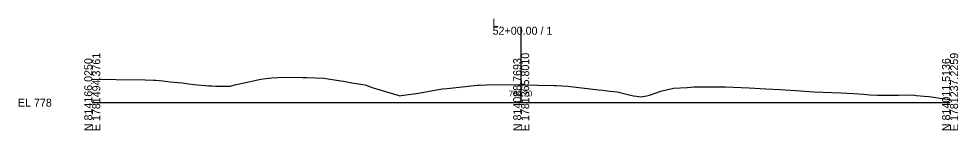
# Model space of a CAD drawing. Extents: x -26 to 7903, y -10 to 9573.
# Drawn here: x 1974.3 to 2302.8, y 2990.3 to 3029.4 of the extents above; entities that cross this region are included whole.
import ezdxf

# ---------------------------------------------------------------- set-up
doc = ezdxf.new("R2010")
doc.units = 0
for name, color, linetype in [('Exist Cross Section Cell', 7, 'Continuous'), ('Exist XS Center Line Elevation Label', 7, 'Continuous'), ('Exist XS Ground Line', 7, 'Continuous')]:
    doc.layers.add(name, color=color, linetype=linetype)

msp = doc.modelspace()

# ---------------------------------------------------------------- linework, layer by layer
at = {"layer": 'Exist Cross Section Cell'}
for p, q in [((2150, 3000), (2150, 3026.63)), ((2000, 3000), (2150, 3000)), ((2150, 3000), (2300, 3000))]:
    msp.add_line(p, q, dxfattribs=at)
at = {"layer": 'Exist XS Ground Line'}
for p, q in [((2000, 3008.11), (2006.24, 3008.2)), ((2006.24, 3008.2), (2008.4, 3008.17)), ((2008.4, 3008.17), (2018.52, 3008.04)), ((2018.52, 3008.04), (2021.46, 3007.89)), ((2021.46, 3007.89), (2022.12, 3007.86)), ((2022.12, 3007.86), (2024.74, 3007.6)), ((2024.74, 3007.6), (2027.24, 3007.27)), ((2027.24, 3007.27), (2031.44, 3006.93)), ((2031.44, 3006.93), (2033.77, 3006.64)), ((2033.77, 3006.64), (2035.53, 3006.38)), ((2035.53, 3006.38), (2040.77, 3005.93)), ((2048.29, 3005.8), (2049.88, 3006.21)), ((2049.88, 3006.21), (2052.52, 3006.83)), ((2052.52, 3006.83), (2059, 3008.25)), ((2059, 3008.25), (2060.66, 3008.51)), ((2060.66, 3008.51), (2062.84, 3008.67)), ((2062.84, 3008.67), (2064.95, 3008.87)), ((2064.95, 3008.87), (2068.12, 3008.88)), ((2068.12, 3008.88), (2073.37, 3008.86)), ((2073.37, 3008.86), (2075.04, 3008.83)), ((2075.04, 3008.83), (2081, 3008.58)), ((2081, 3008.58), (2086.99, 3007.61)), ((2086.99, 3007.61), (2087.84, 3007.48)), ((2087.84, 3007.48), (2090.8, 3006.98)), ((2090.8, 3006.98), (2095.48, 3006.27)), ((2095.48, 3006.27), (2098.19, 3005.24)), ((2134.58, 3006.07), (2135.28, 3006.15)), ((2135.28, 3006.15), (2137.85, 3006.3)), ((2137.85, 3006.3), (2138.44, 3006.33)), ((2138.44, 3006.33), (2150.01, 3006.2)), ((2150.01, 3006.2), (2161.41, 3006)), ((2040.77, 3005.93), (2041.69, 3005.84)), ((2041.69, 3005.84), (2043.16, 3005.76)), ((2043.16, 3005.76), (2047.49, 3005.73)), ((2047.49, 3005.73), (2048.29, 3005.8)), ((2098.19, 3005.24), (2100.21, 3004.58)), ((2100.21, 3004.58), (2104.89, 3003.19)), ((2104.89, 3003.19), (2106.89, 3002.66)), ((2108.04, 3002.46), (2114.15, 3003.35)), ((2114.15, 3003.35), (2120.42, 3004.5)), ((2120.42, 3004.5), (2122.43, 3004.89)), ((2122.43, 3004.89), (2124.12, 3005.01)), ((2124.12, 3005.01), (2133.6, 3005.98)), ((2133.6, 3005.98), (2134.58, 3006.07)), ((2161.41, 3006), (2162.25, 3005.98)), ((2162.25, 3005.98), (2166.26, 3005.75)), ((2166.26, 3005.75), (2177.01, 3004.5)), ((2177.01, 3004.5), (2178.55, 3004.33)), ((2178.55, 3004.33), (2181.01, 3004.08)), ((2181.01, 3004.08), (2183.54, 3003.77)), ((2183.54, 3003.77), (2187.79, 3002.79)), ((2194.83, 3002.64), (2198.82, 3003.97)), ((2198.82, 3003.97), (2203.29, 3005.12)), ((2203.29, 3005.12), (2208.03, 3005.33)), ((2208.03, 3005.33), (2210.41, 3005.49)), ((2210.41, 3005.49), (2219.06, 3005.53)), ((2219.06, 3005.53), (2219.6, 3005.55)), ((2219.6, 3005.55), (2221.51, 3005.57)), ((2221.51, 3005.57), (2229.73, 3005.25)), ((2229.73, 3005.25), (2235.55, 3004.86)), ((2235.55, 3004.86), (2240.55, 3004.66)), ((2240.55, 3004.66), (2247.74, 3004.11)), ((2247.74, 3004.11), (2252.4, 3003.84)), ((2252.4, 3003.84), (2261.77, 3003.43)), ((2261.77, 3003.43), (2264.02, 3003.34)), ((2264.02, 3003.34), (2266.17, 3003.15)), ((2266.17, 3003.15), (2269.87, 3002.93)), ((2269.87, 3002.93), (2271.94, 3002.71)), ((2106.89, 3002.66), (2107.59, 3002.38)), ((2107.59, 3002.38), (2108.04, 3002.46)), ((2187.79, 3002.79), (2189.34, 3002.44)), ((2189.34, 3002.44), (2190.31, 3002.29)), ((2190.31, 3002.29), (2192.02, 3002.06)), ((2192.02, 3002.06), (2193.85, 3002.41)), ((2193.85, 3002.41), (2194.83, 3002.64)), ((2271.94, 3002.71), (2274.57, 3002.62)), ((2274.57, 3002.62), (2277.6, 3002.62)), ((2277.6, 3002.62), (2280.51, 3002.62)), ((2280.51, 3002.62), (2281.91, 3002.65)), ((2281.91, 3002.65), (2287.1, 3002.72)), ((2287.1, 3002.72), (2288.22, 3002.51)), ((2288.22, 3002.51), (2290.88, 3002.29)), ((2290.88, 3002.29), (2292.53, 3002.18)), ((2292.53, 3002.18), (2299.01, 3001.21)), ((2299.01, 3001.21), (2300, 3001.07))]:
    msp.add_line(p, q, dxfattribs=at)

# ---------------------------------------------------------------- texts
at = {"layer": 'Exist Cross Section Cell'}
for s, p in [('L', (2140, 3026.63)), ('52+00.00 / 1', (2140, 3023.83)), ('EL 778', (1974, 2998.6))]:
    msp.add_text(s, height=2.8, dxfattribs=at).set_placement(p)
for s, p in [('E 1781494.3761', (2002.8, 2990)), ('E 1781365.8010', (2152.8, 2990)), ('E 1781237.2259', (2302.8, 2990)), ('N 814166.0250', (2000, 2990)), ('N 814088.7693', (2150, 2990)), ('N 814011.5136', (2300, 2990))]:
    msp.add_text(s, height=2.8, rotation=90, dxfattribs=at).set_placement(p)
at = {"layer": 'Exist XS Center Line Elevation Label'}
msp.add_text('784.20', height=2, dxfattribs=at).set_placement((2145.71, 3002.2))

doc.saveas('drawing.dxf')
